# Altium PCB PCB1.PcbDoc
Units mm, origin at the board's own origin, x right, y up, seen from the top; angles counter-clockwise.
Board outline 20 x 39 mm, 2 copper layers (Top Layer, Bottom Layer); 35 components, 21 nets, 117 pads, 40 vias.
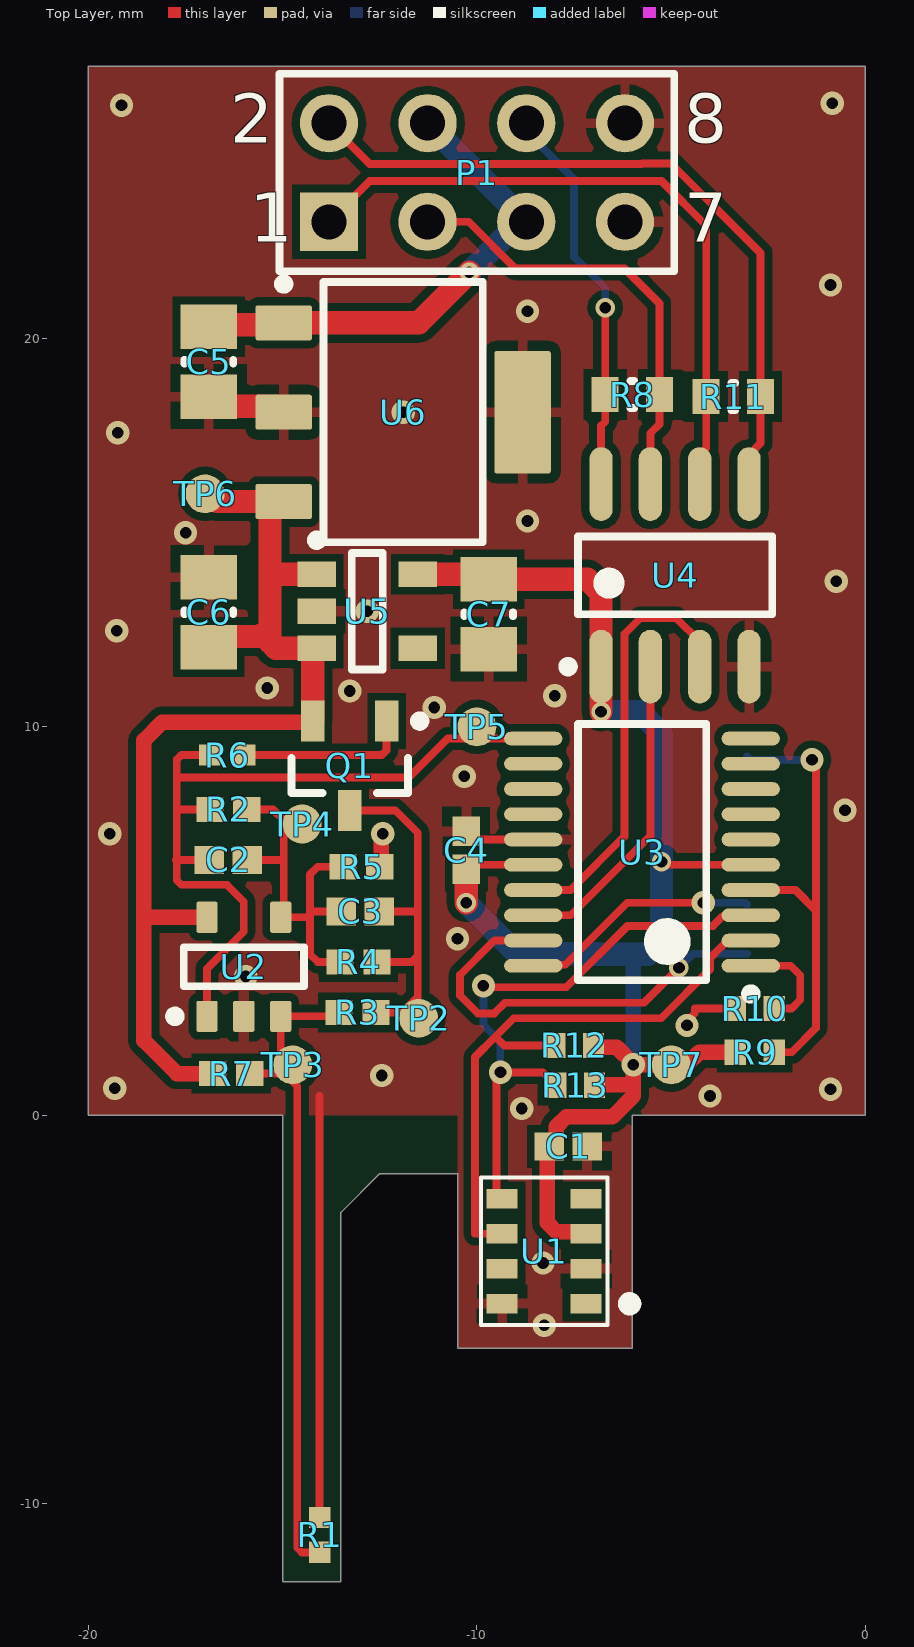
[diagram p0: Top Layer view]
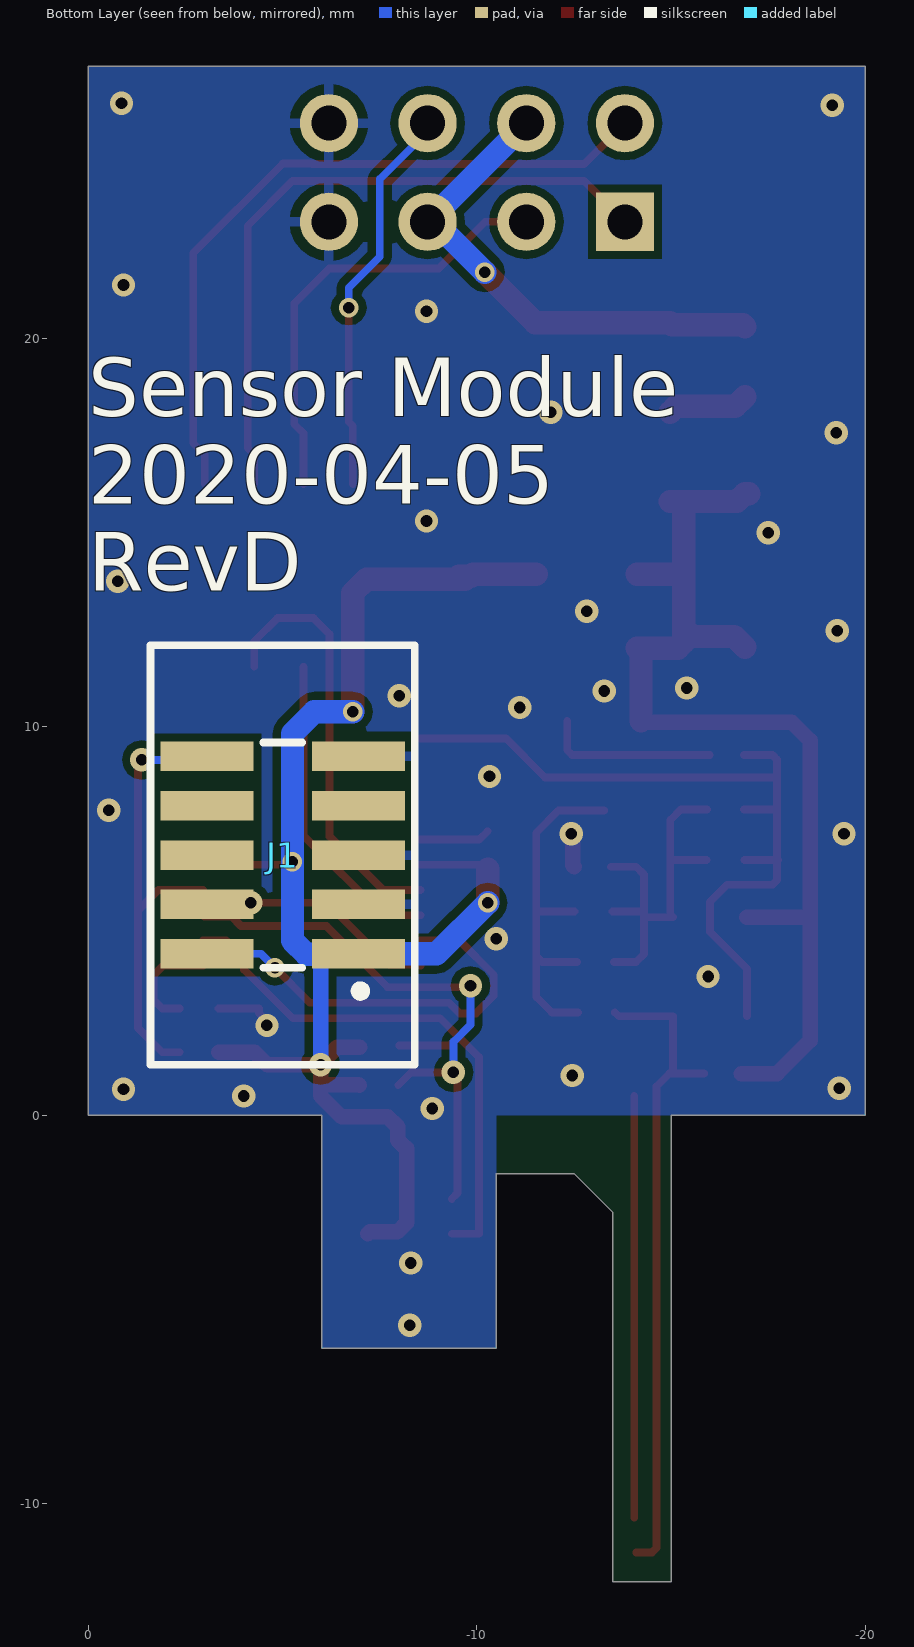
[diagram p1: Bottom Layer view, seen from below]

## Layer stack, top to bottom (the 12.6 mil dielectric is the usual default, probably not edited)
Top Solder: solder mask 0.0102, Solder Resist, Dk 3.5
Top Layer: signal copper 0.0356
Dielectric 1: dielectric 0.32, FR-4, Dk 4.8
Bottom Layer: signal copper 0.0356
Bottom Solder: solder mask 0.0102, Solder Resist, Dk 3.5

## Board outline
-15,-12 -15,0 -20,0 -20,27 0,27 0,0 -6,0 -6,-6 -10.5,-6 -10.5,-1.5 -12.5,-1.5 -13.5,-2.5 -13.5,-12

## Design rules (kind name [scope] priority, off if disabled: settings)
Clearance [All] p1: gap=0.2 ignorepadtopadclearanceinfootprint=FALSE
PolygonConnect [All] p1: thpad.connectstyle=Relief thpad.reliefconductorwidth=0.254 thpad.reliefentries=4 thpad.polygonreliefangle="90 Angle" thpad.airgapwidth=0.254 smdpad.connectstyle=Relief smdpad.reliefconductorwidth=0.254 smdpad.reliefentries=4 smdpad.polygonreliefangle="90 Angle" smdpad.airgapwidth=0.254 via.connectstyle=Direct via.reliefconductorwidth=0.254 via.reliefentries=4 via.polygonreliefangle="90 Angle" via.airgapwidth=0.254
RoomDefinition Sheet1 [InComponentClass('Sheet1')] p1: confinementstyle=ConfineIn formatcopy=TRUE lockcomponents=FALSE outline -20,-12 0,-12 0,27 -20,27
RoutingVias [All] p1: holewidth=0.3 width=0.6 viastyle="Through Hole" minholewidth=0.3 minwidth=0.5 maxholewidth=0.711 maxwidth=1.27
SolderMaskExpansion SolderMaskExpansion_1 [IsVia] p1: expansion=-999 istentingtop=FALSE
SolderMaskExpansion [All] p2: expansion=0.102 istentingtop=FALSE
Width [All] p1: maxlimit=0.6 minlimit=0.2 preferedwidth=0.4
30 further rules are at their usual default settings.

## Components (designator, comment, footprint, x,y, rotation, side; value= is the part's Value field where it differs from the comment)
C1 "GRM155R71C104KA88D" CAPC1005X55X25ML05T10 -7.65,-0.8 r180 top
C2 "100nF" CAPC1005X55X25ML05T10 -16.4,6.575 r0 top
C3 "1uF" CAPC1005X55X25ML05T10 -13,5.25 r180 top
C4 "GRM155R71C104KA88D" CAPC1005X55X25ML05T10 -10.275,6.825 r270 top
C5 "CAP 10uF 10V 0805(2012)" CAPC0805(2012)145_N -16.9,19.4 r90 top value=10uF
C6 "CAP 10uF 10V 0805(2012)" CAPC0805(2012)145_N -16.9,12.95 r270 top value=10uF
C7 "CAP 10uF 10V 0805(2012)" CAPC0805(2012)145_N -9.7,12.9 r90 top value=10uF
J1 "ARM Cortex JTAG" "1.27mm 2x5 SMD Header - no paste" -5,6.7 r90 bottom
P1 "Header 4X2" HDR2X4 -13.81,23 r0 top
Q1 "SMBT2907A" INF-SOT23_N -13.275,9 r270 top
R1 "NTC470, B=3380" RESC1005X40X25NL05T05 -14.05,-10.8 r270 top
R2 "10M 1%" RESC1005X40X25ML05T10 -16.4,7.875 r0 top
R3 "2R21 0.1%" RESC1005X40X25ML05T10 -13.075,2.65 r0 top
R4 "2K 0.1%" RESC1005X40X25ML05T10 -13.05,3.95 r0 top
R5 "75K 0.1%" RESC1005X40X25ML05T10 -12.975,6.4 r180 top
R6 "2K 1%" RESC1005X40X25NL05T05 -16.425,9.275 r180 top
R7 "100K 1%" RESC1005X40X25ML05T10 -16.325,1.075 r0 top
R8 "120R 5% 0603(1608)" RESC0603(1608)_L -6,18.555 r180 top value="120.00 Ohm"
R9 "10K 5% 0402(1005)" RESC0402(1005)_N -2.85,1.625 r0 top value="10000.00 Ohm"
R10 "10K 5% 0402(1005)" RESC0402(1005)_N -2.85,2.75 r180 top value="10000.00 Ohm"
R11 "120R 5% 0603(1608)" RESC0603(1608)_L -3.4,18.5 r0 top value="120.00 Ohm"
R12 "2K2 5% 0402(1005)" RESC0402(1005)_N -7.5,1.8 r0 top value="2200.00 Ohm"
R13 "2K2 5% 0402(1005)" RESC0402(1005)_N -7.475,0.775 r0 top value="2200.00 Ohm"
TP2 "TEST_POINT" TP-SMD-1mm -11.5,2.5 r270 top
TP3 "TEST_POINT" TP-SMD-1mm -14.744,1.302 r270 top
TP4 "TEST_POINT" TP-SMD-1mm -14.5,7.5 r270 top
TP5 "TEST_POINT" TP-SMD-1mm -10,10 r270 top
TP6 "TEST_POINT" TP-SMD-1mm -17,16 r270 top
TP7 "TEST_POINT" TP-SMD-1mm -5,1.3 r270 top
U1 "HP203B" HP203B -8.27,-3.5 r180 top
U2 "TLV2471IDBVT" DBV0005A_L -16,3.825 r90 top
U3 "STM32F030F4P6" STM-TSSOP20_L -5.75,6.775 r180 top
U4 "ADM3488ARZ" ADI-R-8_L -4.9,13.9 r90 top
U5 "MIC5504-3.3YM5-TR" MCHP-SOT-23-M5_V -12.825,12.975 r0 top
U6 "LM2940IMP-9.0/NOPB" DCY0004A_L -11.9,18.1 r0 top

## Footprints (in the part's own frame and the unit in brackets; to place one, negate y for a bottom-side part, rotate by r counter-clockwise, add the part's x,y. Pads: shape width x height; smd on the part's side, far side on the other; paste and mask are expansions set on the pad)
"1.27mm 2x5 SMD Header - no paste" [mm]
  rect 0.76x2.4 smd paste-99: 1(-2.54,-1.95) 2(-2.54,1.95) 3(-1.27,-1.95) 4(-1.27,1.95) 5(0,-1.95) 6(0,1.95) 7(1.27,-1.95) 8(1.27,1.95) 9(2.54,-1.95) 10(2.54,1.95)
  silkscreen extent -5.4,-3.4 5.4,3.4
ADI-R-8_L [mm] "SOIC, 8-Leads, Body 5x4mm, Pitch 1.27mm, IPC High Density"
  oval 1.9x0.6 smd: 1(-2.35,1.905) 2(-2.35,0.635) 3(-2.35,-0.635) 4(-2.35,-1.905) 5(2.35,-1.905) 6(2.35,-0.635) 7(2.35,0.635) 8(2.35,1.905)
  silkscreen extent -2.47,-2.5 1,2.88, body extent -2,-2.5 2,2.5, height 1.75
CAPC0805(2012)145_N [mm] "Chip Capacitor, Body 2.0x1.2mm, Height 1.45mm, IPC Medium Density"
  rect 1.15x1.45 smd: 1(-0.9,0) 2(0.9,0)
  silkscreen extent -0.05,-0.62 0.05,0.63, body extent -1.1,-0.72 1.1,0.73, height 1.45
CAPC1005X55X25ML05T10 [mm] "Chip Capacitor, 2-Leads, Body 1.00x0.50mm, IPC Low Density"
  rect 0.76x0.72 smd: 1(-0.49,0) 2(0.49,0)
  body extent -0.53,-0.28 0.53,0.27, height 0.55
DBV0005A_L [mm] "SOT23, 5-Leads, Body 3.05x1.75mm, Pitch 0.95mm, IPC High Density"
  rrect18% 0.8x0.55 smd: 1(-1.275,0.95) 2(-1.275,0) 3(-1.275,-0.95) 4(1.275,-0.95) 5(1.275,0.95)
  silkscreen extent -1.4,-1.55 0.5,1.9, body extent -1.42,-1.46 1.42,1.46, height 1.08
DCY0004A_L [mm] "SOT223, 4-Leads, Body 6.7x3.7mm, Pitch 2.3mm, IPC High Density"
  rrect11% 1.45x0.9 smd: 1(-3.075,2.3) 2(-3.075,0) 3(-3.075,-2.3)
  rrect7% 1.45x3.15 smd: 4(3.075,0)
  silkscreen extent -3.2,-3.35 2.05,3.42, body extent -3.5,-3.25 3.5,3.25, height 1.62
HDR2X4 [mm] "Connector; Header; 4x2 Position"
  rect 1.5x1.5 hole 0.9: 1(0,0)
  round 1.5 hole 0.9: 2(0,2.54) 3(2.54,0) 4(2.54,2.54) 5(5.08,0) 6(5.08,2.54) 7(7.62,0) 8(7.62,2.54)
  silkscreen extent -1.27,-1.27 8.89,3.81
HP203B [mm] "PRECISION BAROMETER AND ALTIMETER SENSOR"
  rect 0.8x0.5 smd: 1(-1.08,1.35) 2(-1.08,0.45) 3(-1.08,-0.45) 4(-1.08,-1.35) 5(1.08,-1.35) 6(1.08,-0.45) 7(1.08,0.45) 8(1.08,1.35)
  silkscreen extent -2.35,-1.9 1.63,1.9, body extent -1.63,-1.9 1.63,1.9, height 1.2
INF-SOT23_N [mm] "SOT23, 3-Leads, Body 2.9x1.3 mm, Pitch 0.95 mm, IPC Medium Density"
  rect 1.05x0.6 smd: 1(-1.15,0.95) 2(-1.15,-0.95) 3(1.15,0)
  silkscreen extent -1.27,-1.5 0.7,1.93, body extent -0.7,-1.5 0.7,1.5, height 1.1
MCHP-SOT-23-M5_V [mm] "SOT-23, 5-Leads, Body 3x1.7mm, Pitch 0.95mm"
  rect 1x0.66 smd: 1(-1.3,0.95) 2(-1.3,0) 3(-1.3,-0.95) 4(1.3,-0.95) 5(1.3,0.95)
  silkscreen extent -1.42,-1.5 0.4,1.95, body extent -1.5,-1.5 1.5,1.5, height 1.45
RESC0402(1005)_N [mm] "Chip Resistor, Body 1.0x0.5mm, IPC Medium Density"
  rect 0.55x0.65 smd: 1(-0.5,0) 2(0.5,0)
  body extent -0.52,-0.27 0.53,0.28, height 0.4
RESC0603(1608)_L [mm] "Chip Resistor, Body 1.6x0.8mm, IPC High Density"
  rect 0.7x0.9 smd: 1(-0.7,0) 2(0.7,0)
  silkscreen extent -0.05,-0.35 0.05,0.35, body extent -0.85,-0.47 0.85,0.47, height 0.6
RESC1005X40X25ML05T10 [mm] "Chip Resistor, 2-Leads, Body 1.00x0.50mm, IPC Low Density"
  rect 0.7x0.65 smd: 1(-0.475,0) 2(0.475,0)
  body extent -0.53,-0.27 0.53,0.28, height 0.4
RESC1005X40X25NL05T05 [mm] "Chip Resistor, 2-Leads, Body 1.00x0.50mm, IPC Medium Density"
  rect 0.55x0.55 smd: 1(-0.45,0) 2(0.45,0)
  body extent -0.53,-0.27 0.53,0.28, height 0.4
STM-TSSOP20_L [mm] "SOP, 20-Leads, Body 6.6x4.5mm, Pitch 0.65mm, IPC High Density"
  oval 1.5x0.35 smd: 1(-2.8,2.925) 2(-2.8,2.275) 3(-2.8,1.625) 4(-2.8,0.975) 5(-2.8,0.325) 6(-2.8,-0.325) 7(-2.8,-0.975) 8(-2.8,-1.625) 9(-2.8,-2.275) 10(-2.8,-2.925) 11(2.8,-2.925) 12(2.8,-2.275) 13(2.8,-1.625) 14(2.8,-0.975) 15(2.8,-0.325) 16(2.8,0.325) 17(2.8,0.975) 18(2.8,1.625) 19(2.8,2.275) 20(2.8,2.925)
  silkscreen extent -2.93,-3.3 1.65,3.77, body extent -2.25,-3.3 2.25,3.3, height 1.2
TP-SMD-1mm [mm] "Test point, round, 1mm, SMD"
  round 1 smd paste-999: 1(0,0)

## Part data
C1 C3 C4: library part CMP-2100-03641-1, "Chip Capacitor, 0.1 uF, +/- 10%, 16 V, -55 to 125 degC, 0402 (1005 Metric), RoHS, Tape and Reel", Capacitance=100nF, Case Code (Imperial)=0402, Case Code (Metric)=1005, Dielectric=X7R, Dielectric Material=Ceramic, Insulation Resistance=10GR, Manufacturer=Murata, Max Operating Temperature=125degC, Min Operating Temperature=-55degC, Package Description="2-Pin Surface Mount Device, Body 1 x 0.5 mm", Package Quantity=1, Tolerance=10%, Voltage=16V
C2: library part CMP-2100-03641-1, "Chip Capacitor, 0.1 uF, +/- 10%, 16 V, -55 to 125 degC, 0402 (1005 Metric), RoHS, Tape and Reel", Case Code (Imperial)=0402, Case Code (Metric)=1005, Dielectric=X7R, Dielectric Material=Ceramic, Insulation Resistance=10GR, Manufacturer=Murata, Max Operating Temperature=125degC, Min Operating Temperature=-55degC, Package Description="2-Pin Surface Mount Device, Body 1 x 0.5 mm", Package Quantity=1, Tolerance=10%, Voltage=16V
C5 C6 C7: library part CMP-1036-04922-1, "CAP 10uF 10V ±10% 0805 (2012 Metric) Thickness 1.45mm SMD", Case-EIA=0805, Case-Metric=2012, Rated Voltage="10 V", Tolerance=Â±10%
J1: "Arm Cortex 10-pin JTAG connector", Manufacturer=Unknown/Generic, PartNumber=unknown/Generic
P1: "Header, 4-Pin, Dual row"
Q1: library part CMP-1178-00003-1, "PNP Silicon Switching Transistor, 60 V VCEO, 600 mA IC, SOT23, Reel, Green", Manufacturer=Infineon
R1 R6: library part CMP-2002-01187-1, Manufacturer=Panasonic, Part Number=ERT-J0EV474J
R2 R3 R4 R5 R7: library part CMP-2002-07472-1, Manufacturer="Yageo / Phycomp", Part Number=RC0402FR-071KL
R8 R11: library part CMP-1012-00052-1, "120R 0.1W 5% 0603 (1608 Metric)  SMD", Case-EIA=0603, Case-Metric=1608, Power="0.1 W", Tolerance="5 %"
R9 R10: library part CMP-1011-00098-1, "10K 0.063W 5% 0402 (1005 Metric)  SMD", Case-EIA=0402, Case-Metric=1005, Power="0.063 W", Tolerance="5 %"
R12 R13: library part CMP-1011-00082-1, "2K2 0.063W 5% 0402 (1005 Metric)  SMD", Case-EIA=0402, Case-Metric=1005, Power="0.063 W", Tolerance="5 %"
TP2 TP3 TP4 TP5 TP6 TP7: "Test point"
U1: "PRECISION BAROMETER AND ALTIMETER SENSOR", Manufacturer=HopeRF
U2: library part CMP-0271-00230-3, "Single Low-Power Rail-to-Rail Input / Output Operational Amplifier, 2.7 to 6 V, -40 to 125 degC, 5-pin SOT23 (DBV5), Green (RoHS & no Sb/Br)", Manufacturer="Texas Instruments", Total Supply Voltage(Max)(+5V is 5, +/-5V is 10)=6, Total Supply Voltage(Min)(+5V is 5, +/-5V is 10)=2.7
U3: library part CMP-0304-00039-2, "ARM Cortex-M0 32-bit MCU, 16 KB Flash, 4 KB Internal RAM, 15 I/Os, 20-pin TSSOP, -40 to 85 degC, Tube", I/Os (High Current)=15, Operating Frequency(F) (Processor speed) (MHz)=48, Supply Voltage(Vcc) min (V)=2.4
U4: library part CMP-0535-00058-1, "3.3 V Slew Rate Limited, Full-Duplex, RS-485/RS-422 Transceivers, 3 to 3.6 V, -40 to 85 degC, 8-Pin SOIC (R-8), RoHS, Tube", Manufacturer="Analog Devices", Supply Voltage="3 to 3.6 V", Temperature Range="-40 to 85 degC"
U5: library part CMP-2000-07604-1, "Single LDO, 2.5 to 5.5 V, Fixed Out 3.3 V, 0.3 A, -40 to 125 degC, 5-Pin SOT-23 (M5), RoHS, Tape and Reel", Case\/Package=SOT-23, Dropout Voltage=160mV, Manufacturer=Microchip, Max Input Voltage=5.5V, Max Operating Temperature=125degC, Min Current Limit=400mA, Min Input Voltage=2.5V, Min Operating Temperature=-40degC, Nominal Output Voltage=3.3V, Output Current=300mA, Package Description="5-Pin Small Outline Transistor, Body 1.6 x 2.9 mm, Pitch 0.95 mm"
U6: library part CMP-0062-01727-3, "1A Low Dropout Regulator, 4-pin SOT-223, Pb-Free", Manufacturer="Texas Instruments", PackageTopMarking=XYTT*L0EB, PowerWise=N

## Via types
v1: diameter 0.6, hole 0.3, Top Layer to Bottom Layer, 34 vias
v2: diameter 0.5, hole 0.3, Top Layer to Bottom Layer, 6 vias

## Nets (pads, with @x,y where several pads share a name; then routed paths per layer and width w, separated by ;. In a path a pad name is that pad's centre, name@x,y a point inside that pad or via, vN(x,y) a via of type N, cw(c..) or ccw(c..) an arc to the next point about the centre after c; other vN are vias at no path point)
+3.3V: C1.2 C4.2 C7.2 J1.1 R9.1 R12.2 R13.2 TP7.1 U1.3 U3.5 U3.16 U4.1 U5.5 | length 40.5
  Top Layer w0.2: C4.2 -10.16,6.45 U3.16 ; v2(-5.25,6.525) -5.175,6.45 U3.5
  Top Layer w0.4: U1.3 -7.24,-3 -7.953,-3 -8.187,-2.766 -8.187,-0.847 -8.167,-0.847 -7.96,-0.64 -7.96,-0.294 -7.706,-0.04 -6.515,-0.04 -5.975,0.5 -5.975,0.79 ; R12.2@-6.981,1.752 -6.4,1.752 v1@-5.994,1.346 ; R13.2 -6.96,0.79 -5.975,0.79 ; R9.1 -4.278,1.625 -4.603,1.3 v1(-5.975,1.3) -5.975,0.79
  Top Layer w0.6: U5.5 -9.9,13.925 -9.85,13.875 C7.2@-9.53,13.875 ; v2(-10.275,5.475) C4.2 ; C7.2 -7.156,13.8 -6.805,13.449 U4.1 v2(-6.805,10.39)
  Bottom Layer w0.4: J1.1@-6.145,4.15 -5.975,3.98 v1@-5.975,1.346
  Bottom Layer w0.6: v2(-10.275,5.475) -8.96,4.16 J1.1 -6.94,4.15 -6.145,4.15 -5.601,4.15 -5.25,4.501 -5.25,9.827 -5.813,10.39 v2(-6.805,10.39)
+9V: C6.2 Q1.2 R7.1 TP6.1 U2.5 U5.1 U5.3 U6.3 | length 28
  Top Layer w0.4: U2.5 -18.55,5.1 -18.575,5.125 ; R7.1 -17.725,1.075 -18.575,1.925 -18.575,5.125 ; Q1.2 -14.25,10.125 -18.1,10.125 -18.575,9.65 -18.575,5.125
  Top Layer w0.6: TP6.1 -16.892,16 -16.692,15.8 U6.3@-15.175,15.8 ; C6.2 -16.625,12.325 -15.576,12.325 -15.525,12.376 -15.325,12.176 ; U6.3 U6.3@-15.175,15.8 ; Q1.2 -14.225,11.995 U5.3@-14.195,12.025 ; U5.3 U5.3@-14.195,12.025 ; U5.1 -15.325,13.925 ; -15.325,12.176 -15.325,13.925 ; -15.325,12.176 -15.174,12.025 U5.3@-14.195,12.025 ; -15.325,13.925 -15.325,15.65 U6.3@-15.175,15.8
+12V: C5.2 P1.4 P1.5 U6.1 | length 12.9
  Top Layer w0.6: C5.2 -16.85,20.35 -15.025,20.35 U6.1 -11.5,20.4 v2(-10.2,21.7)
  Bottom Layer w0.6: P1.4 P1.5 -8.9,23 v2(-10.2,21.7)
\R\S\T: J1.10 R9.2 U3.4 | length 11.9
  Top Layer w0.2: U3.4 -1.8,5.8 -1.275,5.275 ; R9.2 -1.9,1.625 -1.275,2.25 -1.275,5.275 ; v1(-1.375,9.15) -1.275,9.05 -1.275,5.275
  Bottom Layer w0.2: J1.10 -2.96,9.15 v1(-1.375,9.15)
BOOT0: R10.1 U3.1 | length 2.8
  Top Layer w0.2: U3.1 -1.92,3.85 -1.675,3.605 -1.675,2.975 -1.9,2.75 R10.1
GND: C1.1 C4.1 C5.1 C6.1 C7.1 J1.3 J1.5 J1.9 P1.7 P1.8 R1.1 R5.1 R10.2 U1.2 U1.8 U2.2 U3.15 U4.4 U5.2 U6.2 U6.4 | length 17.2
  Top Layer w0.2: R1.1 -14.05,0.5 ; C4.1 -10.06,7.1 U3.15 ; v1(-4.593,2.315) -4.593,2.427 -4.392,2.628 -4.392,2.75 R10.2
  Top Layer w0.4: R5.1 -12.462,6.438 -12.462,7.213 v1(-12.425,7.25)
  Top Layer w0.6: C5.1 -16.65,18.25 -15.125,18.25 U6.2
  other v1: -8.27,-5.4 -8.3,-3.8 -8.85,0.175 -4,0.5 -19.325,0.7 -0.9,0.675 -12.45,1.025 -15.95,3.575 -10.5,4.55 -19.45,7.25 -0.525,7.85 -10.325,8.725 -11.1,10.5 -8,10.8 -13.275,10.925 -15.4,11 -19.275,12.475 -12.825,12.975 -0.75,13.75 -17.5,15 -8.7,15.3 -19.25,17.575 -11.9,18.1 -8.7,20.7 -0.9,21.375 -19.15,26 -0.85,26.05
I2C1_SCL: R13.1 U1.5 U3.3 | length 15.1
  Top Layer w0.2: v1(-9.833,3.335) -9.785,3.335 -9.75,3.3 -7.7,3.3 -6.125,4.875 -3.927,4.875 -3.681,5.121 -2.979,5.121 U3.3 ; U1.5 -9.5,-2 -9.5,0.999 v1(-9.393,1.107) ; v1@-9.285,1.214 v1(-9.393,1.107) ; R13.1 -8.307,1.107 v1(-9.393,1.107)
  Bottom Layer w0.2: v1(-9.833,3.335) -9.833,2.333 -9.399,1.899 -9.399,1.113 v1(-9.393,1.107)
I2C1_SDA: R12.1 U1.6 U3.2 | length 15.4
  Top Layer w0.2: U1.6 -10.05,-3.05 -10.05,1.503 -9.526,2.026 ; R12.1 -9.3,1.8 -9.526,2.026 ; U3.2 -3.542,4.5 -3.717,4.325 -3.722,4.325 -4,4.047 -4,3.757 -5.257,2.5 -9.053,2.5 -9.526,2.026
NetQ1_1: Q1.1 R6.1 | length 4.5
  Top Layer w0.2: R6.1@-15.991,9.275 -12.45,9.275 -12.325,9.4 Q1.1
SENSE+: R1.2 R3.1 R7.2 TP3.1 U2.3 | length 16.9
  Top Layer w0.2: R7.2 TP3.1@-14.95,1.075 ; R1.2@-14.1,-11.25 -14.508,-11.25 -14.625,-11.133 -14.625,0.75 TP3.1@-14.95,1.075 ; R3.1 -13.65,2.55 U2.3 -15.05,1.175 TP3.1@-14.95,1.075
SENSE-: C2.2 C3.2 R2.2 R4.1 R5.2 TP4.1 U2.4 | length 10
  Top Layer w0.2: R2.2 -15.25,7.875 -14.975,7.6 -14.975,6.6 ; C2.2 -15,6.575 -14.975,6.6 ; R4.1 -14.1,3.95 -14.3,4.15 -14.3,5.1 -14.3,5.175 ; C3.2 -14.225,5.25 -14.3,5.175 ; R5.2 -14.1,6.4 -14.3,6.2 -14.3,5.25 -14.3,5.175 ; -14.975,6.6 -14.975,5.175 U2.4 -14.975,5.1 -14.375,5.1 -14.3,5.175
SENSOR_RX+: P1.3 R8.1 U4.7 | length 11.6
  Top Layer w0.2: P1.3 -10.215,23 -9.015,21.8 -6.2,21.8 -5.3,20.9 R8.1 -5.3,17.792 -5.535,17.558 U4.7
SENSOR_RX-: P1.6 R8.2 U4.8 | length 10.2
  Top Layer w0.2: U4.8 -6.805,17.75 -6.7,17.855 R8.2 v2(-6.7,20.791)
  Bottom Layer w0.2: P1.6 -8.73,25.33 -7.5,24.1 -7.5,22.1 -6.7,21.3 v2(-6.7,20.791)
SENSOR_TX+: P1.1 R11.1 U4.6 | length 17.3
  Top Layer w0.2: P1.1 -12.76,24.05 -5.25,24.05 -4.1,22.9 R11.1 -4.1,17.173 -4.265,17.008 U4.6
SENSOR_TX-: P1.2 R11.2 U4.5 | length 18.6
  Top Layer w0.2: P1.2 -12.76,24.49 -5.755,24.49 -5.745,24.5 -5,24.5 -2.7,22.2 R11.2 -2.7,17.303 -2.995,17.008 U4.5
SWCLK: J1.4 U3.20 | length 6.2
  Top Layer w0.2: U3.20 -8.521,3.879 -7.727,3.879 -6.13,5.475 v1(-4.175,5.475)
  Bottom Layer w0.2: v1(-4.175,5.475) -3.095,5.475 J1.4
SWDIO: J1.2 U3.19 | length 11
  Top Layer w0.2: U3.19 -9.55,4.5 -10.433,3.617 -10.433,3.083 -9.975,2.625 -9.55,2.625 -9.55,2.629 -9.279,2.9 -5.7,2.9 v2(-4.8,3.8)
  Bottom Layer w0.2: v2(-4.8,3.8) -4.44,4.16 J1.2
USART1_RX: U3.18 U4.2 | length 8.2
  Top Layer w0.2: U3.18 -7.587,5.15 -5.535,7.202 U4.2
USART1_TX: U3.17 U4.3 | length 11.1
  Top Layer w0.2: U3.17 -7.586,5.8 -6.205,7.181 -6.205,12.388 -5.793,12.8 -4.865,12.8 -4.265,12.2 U4.3
VBRIDGE: C3.1 Q1.3 R3.2 R4.2 TP2.1 | length 9.6
  Top Layer w0.2: Q1.3 -12.1,7.85 -11.525,7.275 -11.525,5.163 ; R3.2 -11.925,2.65 -11.525,3.05 -11.525,4.106 ; R4.2 -11.681,3.95 -11.525,4.106 ; C3.1 -11.612,5.25 -11.525,5.163 ; -11.525,4.106 -11.525,5.163
VFB: C2.1 R2.1 R6.2 TP5.1 U2.1 U3.11 | length 20.6
  Top Layer w0.2: -17.75,6.575 C2.1 ; U2.1 -16.95,3.775 -16,4.725 -16,5.501 -16.437,5.938 -17.608,5.938 -17.725,6.055 -17.725,7.875 ; R2.1 -17.725,7.875 ; R6.2 -17.608,9.275 -17.725,9.158 -17.725,8.654 ; U3.11 -10.75,9.7 -11.75,8.7 -17.679,8.7 -17.725,8.654 ; -17.725,7.875 -17.725,8.654
pads on no net: J1.6 J1.7 J1.8 U1.1 U1.4 U1.7 U3.6 U3.7 U3.8 U3.9 U3.10 U3.12 U3.13 U3.14 U5.4

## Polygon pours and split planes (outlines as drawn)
GND on Top Layer "GND_L01_P001" (solid, pour order 1): -0.75,-4.5
GND on Top Layer "GND_L01_P000" (solid, remove dead copper, pour order 0): -10.5,-6 -6,-6 -6,0 0,0 0,27 -20,27 -20,0 -10.5,0
GND on Bottom Layer "GND_L02_P002" (solid, pour order 2): -10.5,-6 -6,-6 -6,0 0,0 0,27 -20,27 -20,0 -10.5,0

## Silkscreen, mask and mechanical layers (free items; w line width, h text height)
Bottom Overlay:
  text "Sensor Module / 2020-04-05 / RevD" at 0,13.5 h1.5
Mechanical 1:
  the board outline again, w0.1
Dimensions:
  lines w0.05: -21,-22 3,-22 ; -21,-21 3,-21 ; -21,-1 3,-1 ; -21,0 3,0
  lines w0.1: -18,0 -18,27 ; -7,-9.32 -7,-8.05 ; -5.73,-8.05 -7,-8.05 ; -2,0 -2,27 ; 3.16,-18.21 -7,-8.05
  text "Pressure sensor and thermistor inside tube" at 4.5,-20 h1.25
  text "Tube cutaway" at -32.4,-20.75 h2 r90

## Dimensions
0,27 to 3,0 on Dimensions
-15,-12 to -13.5,-12 on Dimensions
0,27 to -13.5,-12 on Dimensions
0,27 to -20,27 on Dimensions
-21,0 to -21,-11 on Dimensions
-21,0 to -21,-22 on Dimensions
